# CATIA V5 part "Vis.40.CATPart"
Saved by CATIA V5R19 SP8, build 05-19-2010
Part number: Vis.40
Bounding box of the stored display mesh (mm): x -2.963 to 2.963, y -2.818 to 2.818, z -12.5 to 18.5
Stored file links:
  G:\EU_thinkMotion\CFAO_2010\MMS_groupe3\MMS_groupe3\jbonnamy\jbonnamy_cfao\Vis.40.CATPart
  G:\EU_thinkMotion\CFAO_2010\MMS_groupe3\MMS_groupe3\jbonnamy\jbonnamy_cfao\jbonnamy_suspension.arriere.directionnelle.CATProduct
  G:\EU_thinkMotion\CFAO_2010\MMS_groupe3\MMS_groupe3\jbonnamy\jbonnamy_cfao\SKL.general.CATPart
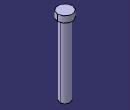
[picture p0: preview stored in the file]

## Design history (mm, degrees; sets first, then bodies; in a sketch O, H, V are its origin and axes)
External parameters (linked from other documents)
  External.Longueur.vis = 28.5 mm
  External.Diametre.vis.12 = 3.95 mm
Set1
  Plane1 "Plan.haut.support.10": linked copy from another document
  Point1 "Centre.pignon": linked copy from another document
Body1 (main body)
  Sketch1 on Plane1, origin (0, 0, 16), H (1, 0, 0), V (0, 1, 0)
    circle A1 centre (0, 0) radius 1.975
    point P1 (0, 0)
    reference projected point E1 (0, 0) from Point1
    radius A1 = 1.975 {= External.Diametre.vis.12 /2}
    distance P1 E1 = 0
  Pad1: profile Sketch1, direction (0, 0, -1), length 28.5 {= External.Longueur.vis}
  Sketch2 on Plane1, origin (0, 0, 16), H (1, 0, 0), V (0, 1, 0)
    circle A1 centre (0, 0) radius 2.9625
    point P1 (0, 0)
    reference projected point E1 (0, 0) from Point1
    radius A1 = 2.9625 {= 3*External.Diametre.vis.12 /4}
    distance P1 E1 = 0
  Pad2: profile Sketch2, direction (0, 0, 1), length 2.5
